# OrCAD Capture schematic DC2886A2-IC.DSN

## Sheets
1 PAGE1: size C; company: ANALOG DEVICES; note: DEMO BOARD BILL OF MATERIALS; note: HIGH POWER POLY-PHASE BI-DIRECTIONAL SUPPLY/CHARGER
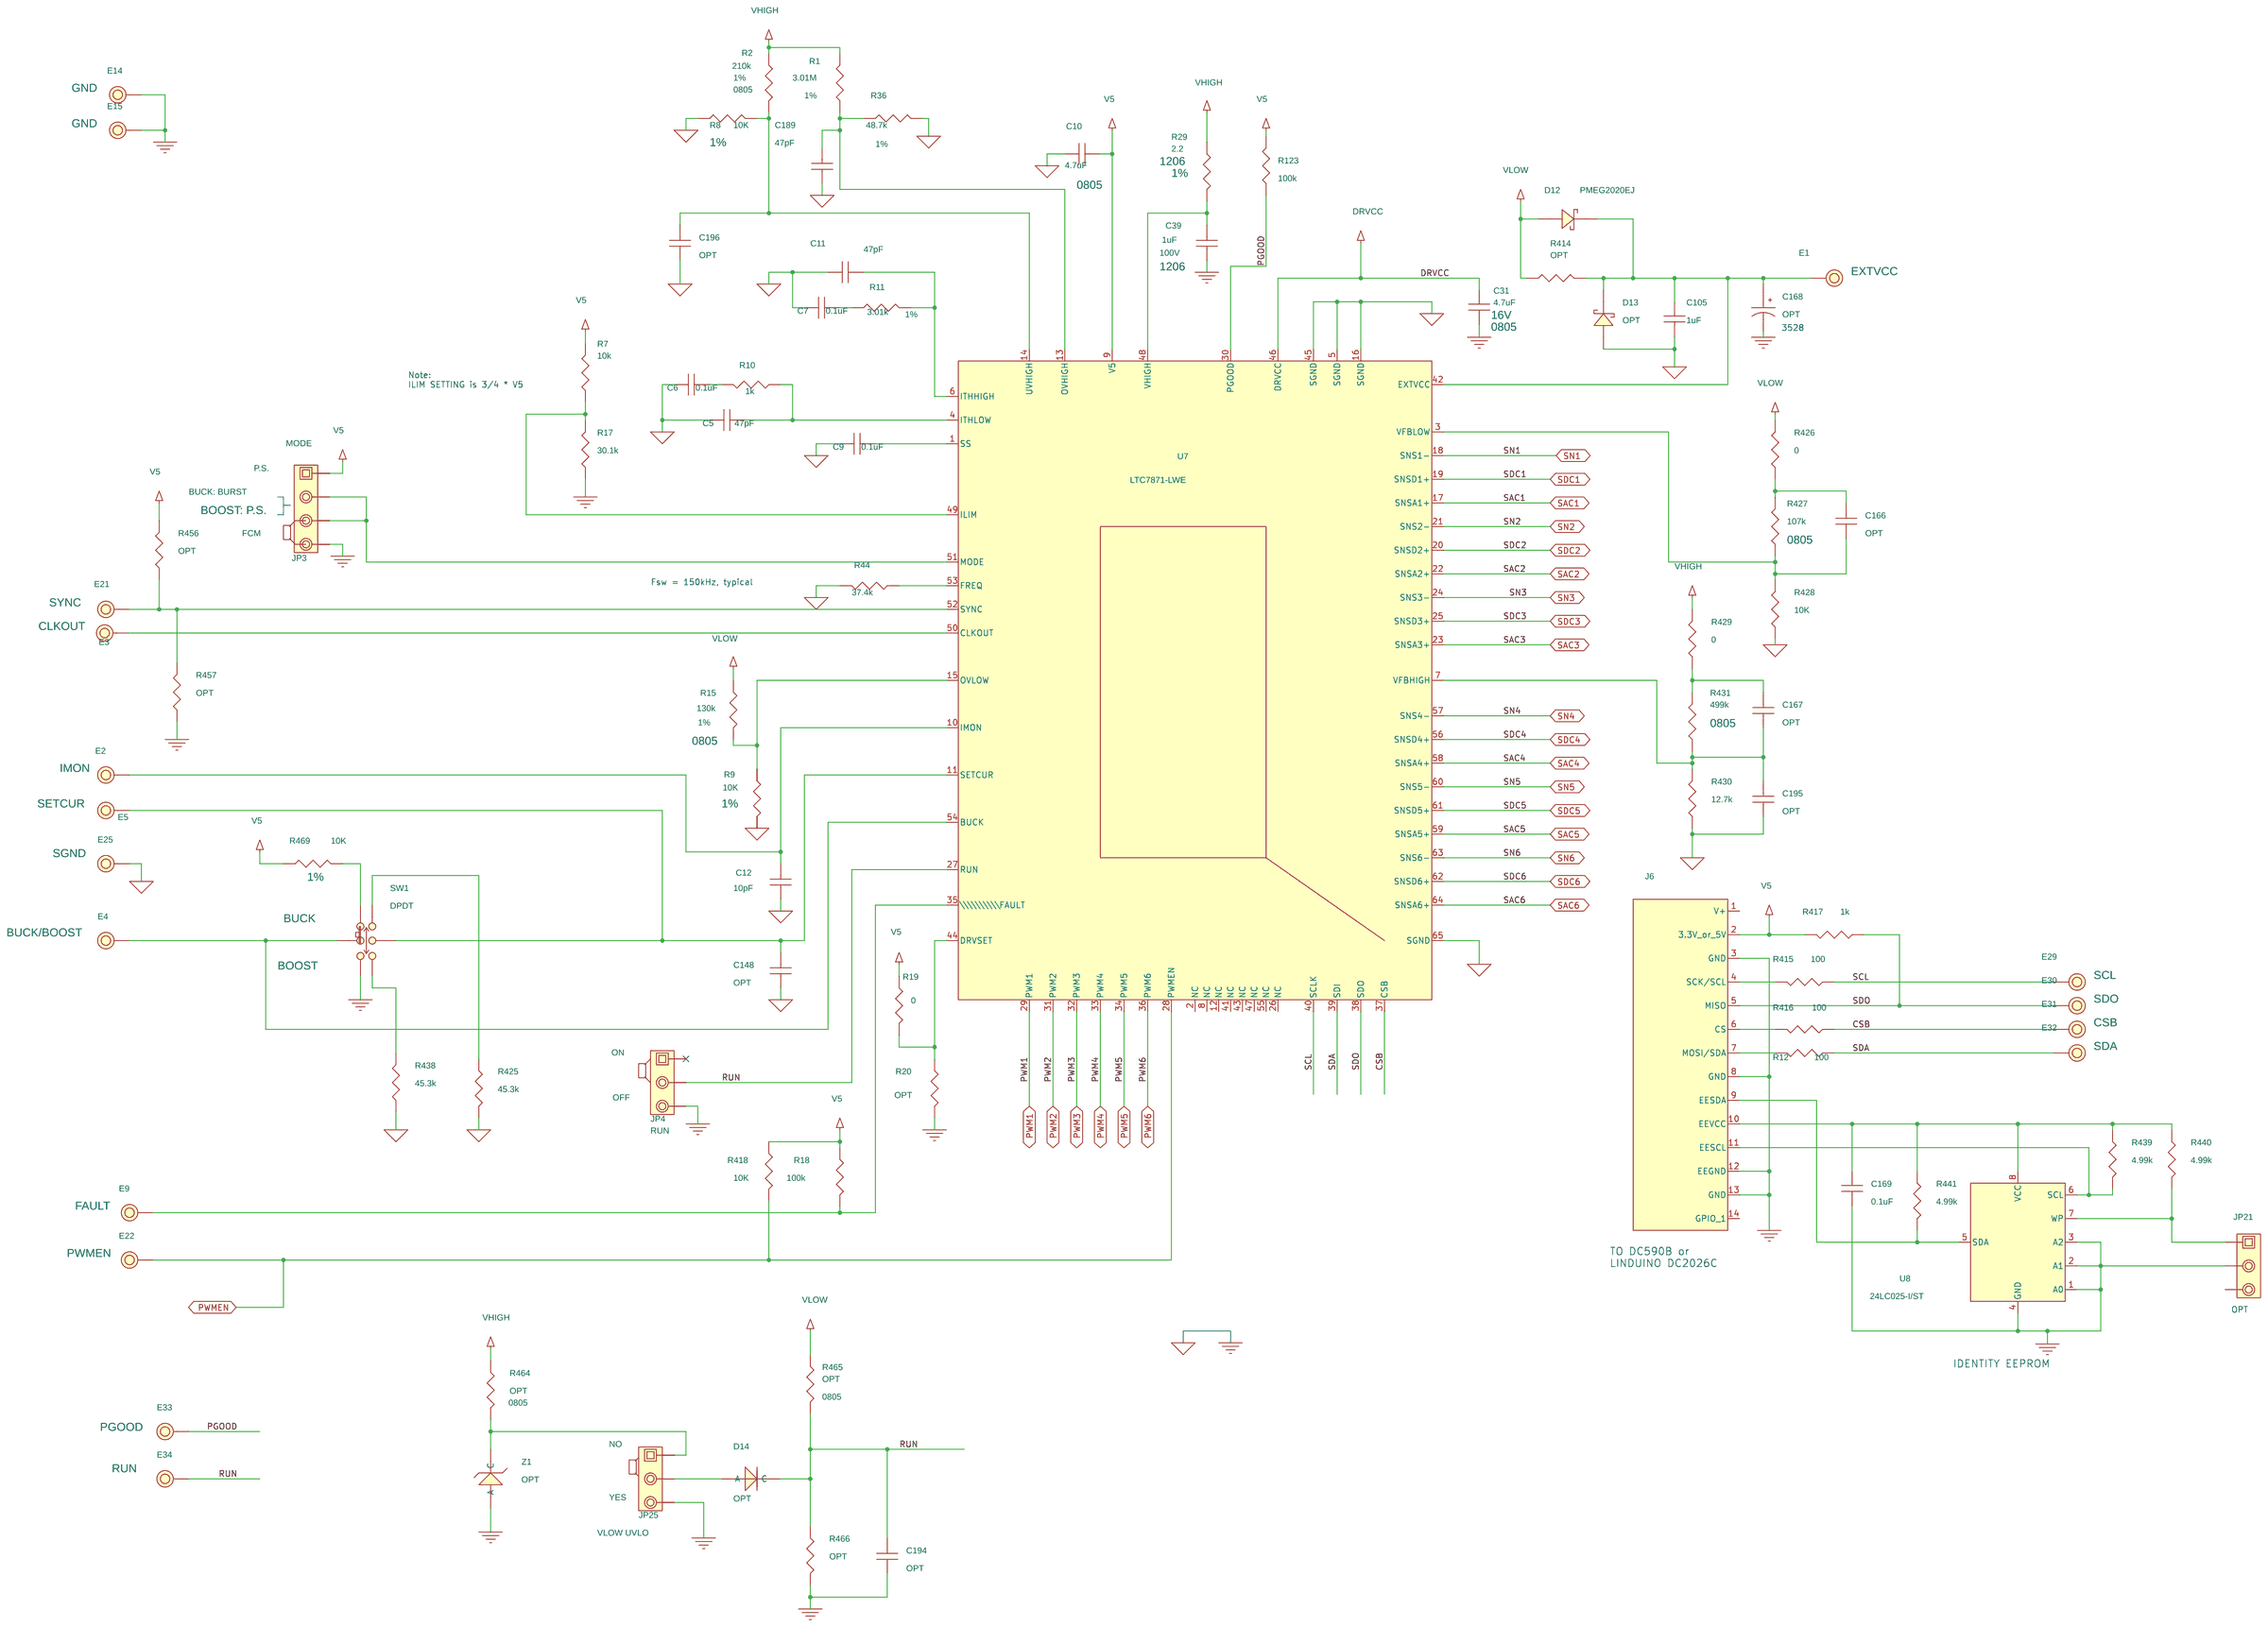
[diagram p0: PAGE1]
2 PAGE2: size C
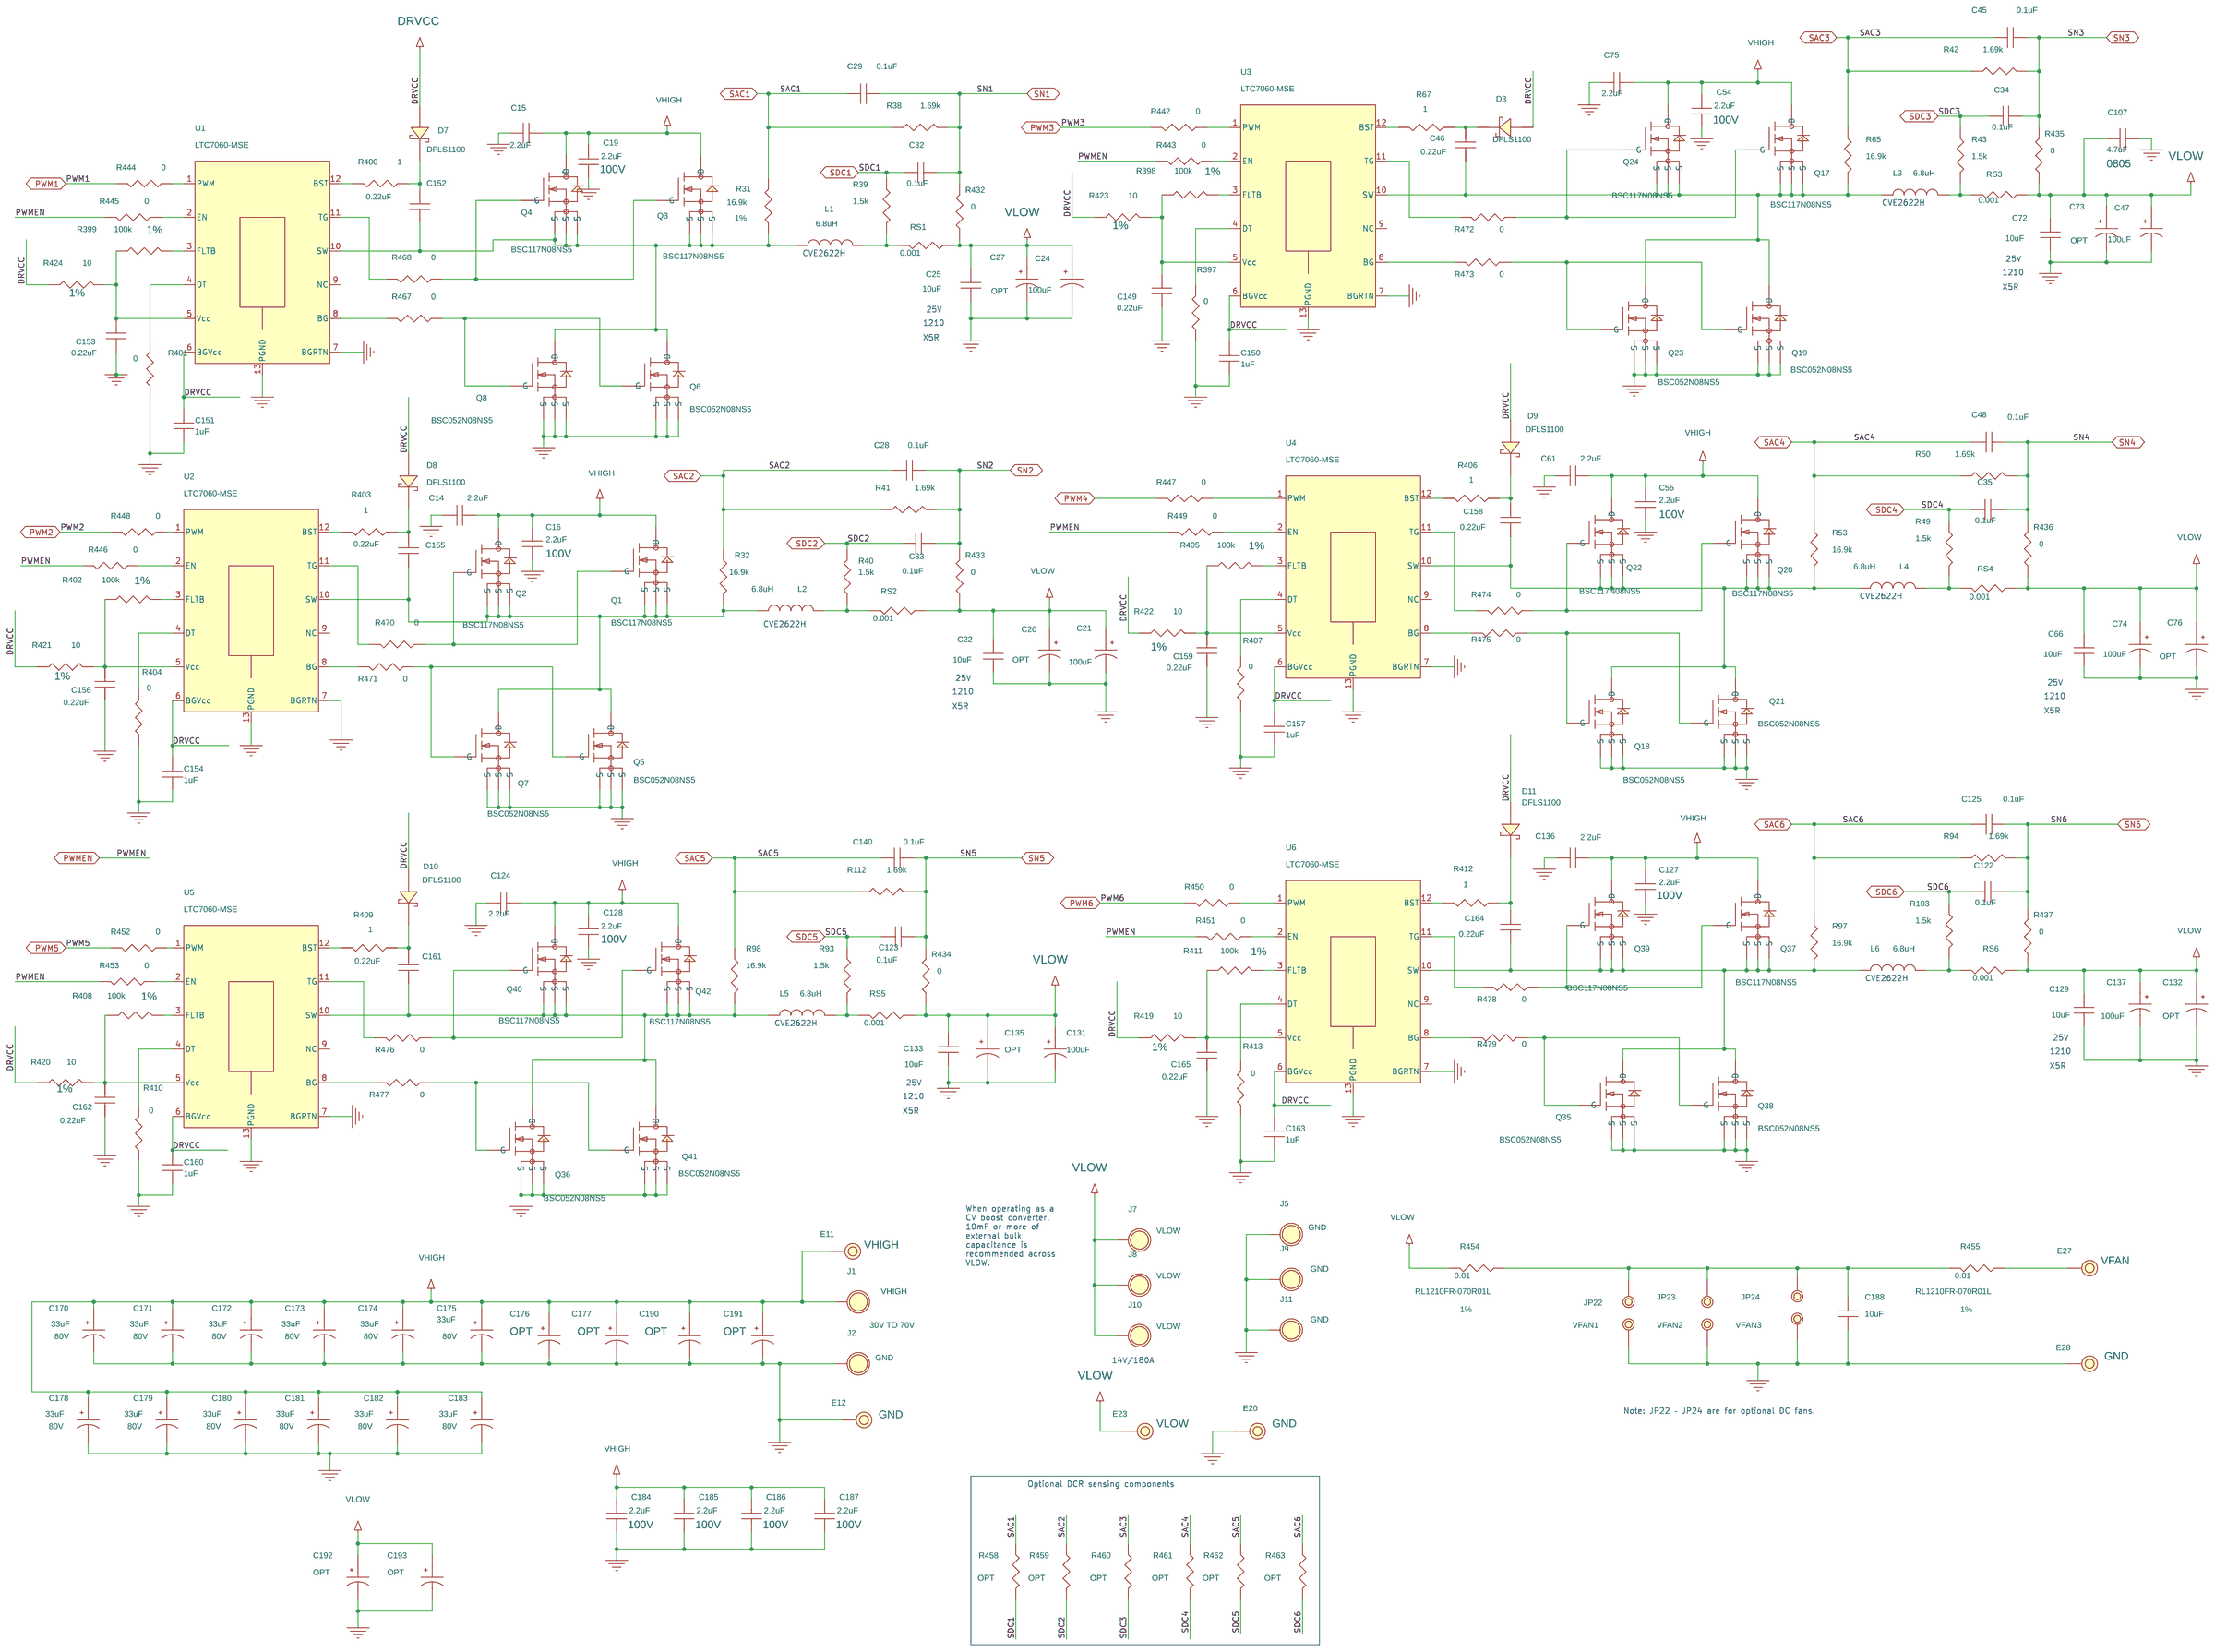
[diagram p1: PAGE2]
3 PAGE3
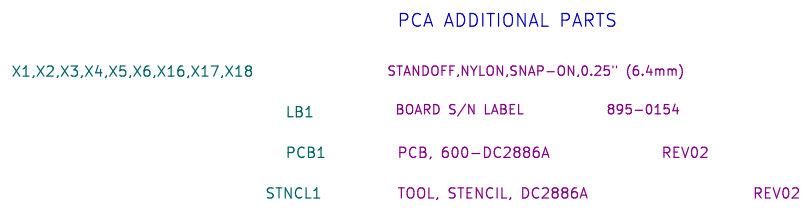
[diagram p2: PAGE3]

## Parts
sheet PAGE1
C5  47pF  [CC0603N]
C6  0.1uF  [CC0603N]
C7  0.1uF  [CC0603N]
C9  0.1uF  [CC0603N]
C10  4.7uF  [CC0805N]
C11  47pF  [CC0603N]
C12  10pF  [CC0603N]
C31  4.7uF  [CC0805N]
C39  1uF  [CC1206N]
C105  1uF  [CC0603N]
C148  OPT  [CC0603N]
C166  OPT  [CC0603N]
C167  OPT  [CC0603N]
C168  OPT  [CAPMP3528N]
C169  0.1uF  [CC0603N]
C189  47pF  [CC0603N]
C194  OPT  [CC0603N]
C195  OPT  [CC0603N]
C196  OPT  [CC0603N]
D12  PMEG2020EJ  [SOD-323F-N]
D13  OPT  [SOD-323N]
D14  OPT  [SOD-323N]
E1  TEST POINT  [MILLMAX2501]
E2  TEST POINT  [MILLMAX2501]
E3  TEST POINT  [MILLMAX2501]
E4  TEST POINT  [MILLMAX2501]
E5  TEST POINT  [MILLMAX2501]
E9  TEST POINT  [MILLMAX2501]
E14  TEST POINT  [MILLMAX2501]
E15  TEST POINT  [MILLMAX2501]
E21  TEST POINT  [MILLMAX2501]
E22  TEST POINT  [MILLMAX2501]
E25  TEST POINT  [MILLMAX2501]
E29  TEST POINT  [MILLMAX2501]
E30  TEST POINT  [MILLMAX2501]
E31  TEST POINT  [MILLMAX2501]
E32  TEST POINT  [MILLMAX2501]
E33  TEST POINT  [MILLMAX2501]
E34  TEST POINT  [MILLMAX2501]
J6  HDR,SHROUDED  [HD2X7-079-MOLEX]
JP3  HDR.  [HD1X4-079]
JP4  HDR  [HD1X3-079]
JP21  HDR  [HD1X3-079]
JP25  HDR  [HD1X3-079]
R1  3.01M  [CR0805N]
R2  210k  [CR0805N]
R7  10k  [CR0603N]
R8  10K  [CR0603N]
R9  10K  [CR0603N]
R10  1k  [CR0603N]
R11  3.01k  [CR0603N]
R12  100  [CR0603N]
R15  130k  [CR0805N]
R17  30.1k  [CR0603N]
R18  100k  [CR0603N]
R19  0  [CR0603N]
R20  OPT  [CR0603N]
R29  2.2  [CR1206N]
R36  48.7k  [CR0603N]
R44  37.4k  [CR0603N]
R123  100k  [CR0603N]
R414  OPT  [CR0603N]
R415  100  [CR0603N]
R416  100  [CR0603N]
R417  100  [CR0603N]
R418  10K  [CR0603N]
R425  45.3k  [CR0603N]
R426  0  [CR0603N]
R427  107k  [CR0805N]
R428  10K  [CR0603N]
R429  0  [CR0603N]
R430  12.7k  [CR0603N]
R431  499k  [CR0805N]
R438  45.3k  [CR0603N]
R439  4.99k  [CR0603N]
R440  4.99k  [CR0603N]
R441  4.99k  [CR0603N]
R456  OPT  [CR0603N]
R457  OPT  [CR0603N]
R464  OPT  [CR0805N]
R465  OPT  [CR0805N]
R466  OPT  [CR0805N]
R469  10K  [CR0603N]
SW1  DPDT  [CK-JS202011CQN]
U7  LTC7871-LWE  [LTC-LWE-64-1982]
U8  24LC025-I/ST  [MO-153AA_N]
XJP3  SHUNT
XJP10  SHUNT
XJP11  SHUNT
Z1  OPT  [SOD-123N]
sheet PAGE2
C14  2.2uF  [CC1210N]
C15  2.2uF  [CC1210N]
C16  2.2uF  [CC1210N]
C19  2.2uF  [CC1210N]
C20  OPT  [USER_ASSIGNED]
C21  100uF  [PANASONIC_ZA_6.3X7.7]
C22  10uF  [CC1210N]
C24  100uF  [PANASONIC_ZA_6.3X7.7]
C25  10uF  [CC1210N]
C27  OPT  [USER_ASSIGNED]
C28  0.1uF  [CC0603N]
C29  0.1uF  [CC0603N]
C32  0.1uF  [CC0603N]
C33  0.1uF  [CC0603N]
C34  0.1uF  [CC0603N]
C35  0.1uF  [CC0603N]
C45  0.1uF  [CC0603N]
C46  0.22uF  [CC0603N]
C47  100uF  [PANASONIC_ZA_6.3X7.7]
C48  0.1uF  [CC0603N]
C54  2.2uF  [CC1210N]
C55  2.2uF  [CC1210N]
C61  2.2uF  [CC1210N]
C66  10uF  [CC1210N]
C72  10uF  [CC1210N]
C73  OPT  [USER_ASSIGNED]
C74  100uF  [PANASONIC_ZA_6.3X7.7]
C75  2.2uF  [CC1210N]
C76  OPT  [USER_ASSIGNED]
C107  4.7uF  [CC0805N]
C122  0.1uF  [CC0603N]
C123  0.1uF  [CC0603N]
C124  2.2uF  [CC1210N]
C125  0.1uF  [CC0603N]
C127  2.2uF  [CC1210N]
C128  2.2uF  [CC1210N]
C129  10uF  [CC1210N]
C131  100uF  [PANASONIC_ZA_6.3X7.7]
C132  OPT  [USER_ASSIGNED]
C133  10uF  [CC1210N]
C135  OPT  [USER_ASSIGNED]
C136  2.2uF  [CC1210N]
C137  100uF  [PANASONIC_ZA_6.3X7.7]
C140  0.1uF  [CC0603N]
C149  0.22uF  [CC0603N]
C150  1uF  [CC0603N]
C151  1uF  [CC0603N]
C152  0.22uF  [CC0603N]
C153  0.22uF  [CC0603N]
C154  1uF  [CC0603N]
C155  0.22uF  [CC0603N]
C156  0.22uF  [CC0603N]
C157  1uF  [CC0603N]
C158  0.22uF  [CC0603N]
C159  0.22uF  [CC0603N]
C160  1uF  [CC0603N]
C161  0.22uF  [CC0603N]
C162  0.22uF  [CC0603N]
C163  1uF  [CC0603N]
C164  0.22uF  [CC0603N]
C165  0.22uF  [CC0603N]
C170  33uF  [PANASONIC_ZC_10X10.2]
C171  33uF  [PANASONIC_ZC_10X10.2]
C172  33uF  [PANASONIC_ZC_10X10.2]
C173  33uF  [PANASONIC_ZC_10X10.2]
C174  33uF  [PANASONIC_ZC_10X10.2]
C175  33uF  [PANASONIC_ZC_10X10.2]
C176  100uF  [SUNCON_CE-KX_16X16.5]
C177  100uF  [SUNCON_CE-KX_16X16.5]
C178  33uF  [PANASONIC_ZC_10X10.2]
C179  33uF  [PANASONIC_ZC_10X10.2]
C180  33uF  [PANASONIC_ZC_10X10.2]
C181  33uF  [PANASONIC_ZC_10X10.2]
C182  33uF  [PANASONIC_ZC_10X10.2]
C183  33uF  [PANASONIC_ZC_10X10.2]
C184  2.2uF  [CC1210N]
C185  2.2uF  [CC1210N]
C186  2.2uF  [CC1210N]
C187  2.2uF  [CC1210N]
C188  10uF  [CC1210N]
C190  100uF  [SUNCON_CE-KX_16X16.5]
C191  100uF  [SUNCON_CE-KX_16X16.5]
C192  OPT  [USER_ASSIGNED]
C193  OPT  [USER_ASSIGNED]
D3  DFLS1100  [POWERDI-123]
D7  DFLS1100  [POWERDI-123]
D8  DFLS1100  [POWERDI-123]
D9  DFLS1100  [POWERDI-123]
D10  DFLS1100  [POWERDI-123]
D11  DFLS1100  [POWERDI-123]
E11  TEST POINT  [MILLMAX2501]
E12  TEST POINT  [MILLMAX2501]
E20  TEST POINT  [MILLMAX2501]
E23  TEST POINT  [MILLMAX2501]
E27  TEST POINT  [MILLMAX2501]
E28  TEST POINT  [MILLMAX2501]
J1  STUD,#10-32  [PENN-KFH-032]
J2  STUD,#10-32  [PENN-KFH-032]
J5  STUD,#10-32  [PENN-KFH-032]
J7  STUD,#10-32  [PENN-KFH-032]
J8  STUD,#10-32  [PENN-KFH-032]
J9  STUD,#10-32  [PENN-KFH-032]
J10  STUD,#10-32  [PENN-KFH-032]
J11  STUD,#10-32  [PENN-KFH-032]
JP22  HDR  [HD1X2-100]
JP23  HDR  [HD1X2-100]
JP24  HDR  [HD1X2-100]
L1  6.8uH  [SAGAMI-CVE2622HA-6R8M-R]
L2  6.8uH  [SAGAMI-CVE2622HA-6R8M-R]
L3  6.8uH  [SAGAMI-CVE2622HA-6R8M-R]
L4  6.8uH  [SAGAMI-CVE2622HA-6R8M-R]
L5  6.8uH  [SAGAMI-CVE2622HA-6R8M-R]
L6  6.8uH  [SAGAMI-CVE2622HA-6R8M-R]
Q1  BSC117N08NS5  [INFINEON-PG-TDSON-8]
Q2  BSC117N08NS5  [INFINEON-PG-TDSON-8]
Q3  BSC117N08NS5  [INFINEON-PG-TDSON-8]
Q4  BSC117N08NS5  [INFINEON-PG-TDSON-8]
Q5  BSC052N08NS5  [INFINEON-PG-TDSON-8]
Q6  BSC052N08NS5  [INFINEON-PG-TDSON-8]
Q7  BSC052N08NS5  [INFINEON-PG-TDSON-8]
Q8  BSC052N08NS5  [INFINEON-PG-TDSON-8]
Q17  BSC117N08NS5  [INFINEON-PG-TDSON-8]
Q18  BSC052N08NS5  [INFINEON-PG-TDSON-8]
Q19  BSC052N08NS5  [INFINEON-PG-TDSON-8]
Q20  BSC117N08NS5  [INFINEON-PG-TDSON-8]
Q21  BSC052N08NS5  [INFINEON-PG-TDSON-8]
Q22  BSC117N08NS5  [INFINEON-PG-TDSON-8]
Q23  BSC052N08NS5  [INFINEON-PG-TDSON-8]
Q24  BSC117N08NS5  [INFINEON-PG-TDSON-8]
Q35  BSC052N08NS5  [INFINEON-PG-TDSON-8]
Q36  BSC052N08NS5  [INFINEON-PG-TDSON-8]
Q37  BSC117N08NS5  [INFINEON-PG-TDSON-8]
Q38  BSC052N08NS5  [INFINEON-PG-TDSON-8]
Q39  BSC117N08NS5  [INFINEON-PG-TDSON-8]
Q40  BSC117N08NS5  [INFINEON-PG-TDSON-8]
Q41  BSC052N08NS5  [INFINEON-PG-TDSON-8]
Q42  BSC117N08NS5  [INFINEON-PG-TDSON-8]
R31  16.9k  [CR0805N]
R32  16.9k  [CR0805N]
R38  1.69k  [CR0603N]
R39  1.5k  [CR0603N]
R40  1.5k  [CR0603N]
R41  1.69k  [CR0603N]
R42  1.69k  [CR0603N]
R43  1.5k  [CR0603N]
R49  1.5k  [CR0603N]
R50  1.69k  [CR0603N]
R53  16.9k  [CR0805N]
R65  16.9k  [CR0805N]
R67  1  [CR0603N]
R93  1.5k  [CR0603N]
R94  1.69k  [CR0603N]
R97  16.9k  [CR0805N]
R98  16.9k  [CR0805N]
R103  1.5k  [CR0603N]
R112  1.69k  [CR0603N]
R397  0  [CR0603N]
R398  100k  [CR0603N]
R399  100k  [CR0603N]
R400  1  [CR0603N]
R401  0  [CR0603N]
R402  100k  [CR0603N]
R403  1  [CR0603N]
R404  0  [CR0603N]
R405  100k  [CR0603N]
R406  1  [CR0603N]
R407  0  [CR0603N]
R408  100k  [CR0603N]
R409  1  [CR0603N]
R410  0  [CR0603N]
R411  100k  [CR0603N]
R412  1  [CR0603N]
R413  0  [CR0603N]
R419  10  [CR0603N]
R420  10  [CR0603N]
R421  10  [CR0603N]
R422  10  [CR0603N]
R423  10  [CR0603N]
R424  10  [CR0603N]
R432  0  [CR0603N]
R433  0  [CR0603N]
R434  0  [CR0603N]
R435  0  [CR0603N]
R436  0  [CR0603N]
R437  0  [CR0603N]
R442  0  [CR0603N]
R443  0  [CR0603N]
R444  0  [CR0603N]
R445  0  [CR0603N]
R446  0  [CR0603N]
R447  0  [CR0603N]
R448  0  [CR0603N]
R449  0  [CR0603N]
R450  0  [CR0603N]
R451  0  [CR0603N]
R452  0  [CR0603N]
R453  0  [CR0603N]
R454  0.01  [CR1210N]
R455  0.01  [CR1210N]
R458  OPT  [CR0603N]
R459  OPT  [CR0603N]
R460  OPT  [CR0603N]
R461  OPT  [CR0603N]
R462  OPT  [CR0603N]
R463  OPT  [CR0603N]
R467  0  [CR0603N]
R468  0  [CR0603N]
R470  0  [CR0603N]
R471  0  [CR0603N]
R472  0  [CR0603N]
R473  0  [CR0603N]
R474  0  [CR0603N]
R475  0  [CR0603N]
R476  0  [CR0603N]
R477  0  [CR0603N]
R478  0  [CR0603N]
R479  0  [CR0603N]
RS1  0.001  [VISHAY-WSL2512-T87]
RS2  0.001  [VISHAY-WSL2512-T87]
RS3  0.001  [VISHAY-WSL2512-T87]
RS4  0.001  [VISHAY-WSL2512-T87]
RS5  0.001  [VISHAY-WSL2512-T87]
RS6  0.001  [VISHAY-WSL2512-T87]
U1  LTC7060-MSE  [LTC-MSE-12-1666]
U2  LTC7060-MSE  [LTC-MSE-12-1666]
U3  LTC7060-MSE  [LTC-MSE-12-1666]
U4  LTC7060-MSE  [LTC-MSE-12-1666]
U5  LTC7060-MSE  [LTC-MSE-12-1666]
U6  LTC7060-MSE  [LTC-MSE-12-1666]
sheet PAGE3
LB1  LABEL  [895-0154_REV01]
PCB1  PCB, 600-DC2886A
STNCL1  TOOL, STENCIL, DC2886A
X1,X2,X3,X4,X5,X6,X16,X17,X18  STANDOFF  [MTG-8831]

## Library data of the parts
C5 = CAP: CAP.,47pF,C0G,50V,10%,0603; CLASS: DISCRETE; Dielectric Type: C0G; FPLIST: CC0603N,CC0603L,CC0603M; Inventory Qty: 4550; Manufacturer: AVX; Manufacturer PN: 06035A470KAT2A; PART_NUMBER: 150-3408; Package Size: 0603; Part Number: AVX 06035A470KAT2A; Rated Voltage: 50V; Tolerance: 10%
C6 C7 C9 = CAP: CAP.,0.1uF,X7R,25V,10%,0603,AEC-Q200; CLASS: DISCRETE; Dielectric Type: X7R; FPLIST: CC0603N,CC0603L,CC0603M; Inventory Qty: 5452; Manufacturer: AVX; Manufacturer PN: 06033C104K4T4A; PART_NUMBER: 150-0439; Package Size: 0603; Part Number: AVX 06031C103KAT2A; Rated Voltage: 25V; Tolerance: 10%
C10 C31 C107 = CAP: CAP.,4.7uF,X7R,16V,10%,0805; CLASS: DISCRETE; Dielectric Type: X7R; FPLIST: CC0805N,CC0805L,CC0805M; Inventory Qty: 55550; Manufacturer: AVX; Manufacturer PN: 0805YC475KAT2A; PART_NUMBER: 150-2085; Package Size: 0805; Part Number: AVX 0805YC475KAT2A; Rated Voltage: 16V; Tolerance: 10%
C11 C189 = CAP: CAP.,47pF,C0G,50V,5%,0603; CLASS: DISCRETE; Dielectric Type: C0G; FPLIST: CC0603N,CC0603L,CC0603M; Inventory Qty: 42764; Manufacturer: MURATA; Manufacturer PN: GRM1885C1H470JA01D; PART_NUMBER: 150-0054; Package Size: 0603; Rated Voltage: 50V; Tolerance: 5%
C12 = CAP: CAP.,10pF,C0G,100V,+/-0.1pF,0603; CLASS: DISCRETE; Dielectric Type: C0G; FPLIST: CC0603N,CC0603L,CC0603M; Inventory Qty: 190; Manufacturer: AVX; Manufacturer PN: 06031A100BAT2A; PART_NUMBER: 150-2528; Package Size: 0603; Part Number: AVX 06031A100KAT2A / AVX; Rated Voltage: 100V; Tolerance: +/-0.1pF
C39 = CAP: CAP.,1uF,X7R,100V,10%,1206; CLASS: DISCRETE; Dielectric Type: X7R; FPLIST: CC1206N,CC1206L,CC1206M; Inventory Qty: 11126; Manufacturer: AVX; Manufacturer PN: 12061C105KAT2A; PART_NUMBER: 150-3438; Package Size: 1206; Rated Voltage: 100V; Tolerance: 10%
C105 = CAP: CAP.,1uF,X7R,25V,10%,0603,AEC-Q200; CLASS: DISCRETE; Dielectric Type: X7R; FPLIST: CC0603N,CC0603L,CC0603M; Inventory Qty: 38139; Manufacturer: MURATA; Manufacturer PN: GCM188R71E105KA64D; PART_NUMBER: 150-0291; Package Size: 0603; Part Number: MURATA GRM188R71E105KA12D; Rated Voltage: 25V; Tolerance: 10%
C148 = CAP: CAP., OPTION, 0603; CLASS: DISCRETE; FPLIST: CC0603N,CC0603L,CC0603M; PART_NUMBER: 150-3038; Package Size: 0603; Package Type: SMD; Part Number: AVX 06031A100KAT2A / AVX
C166 C167 = CAP: CAP., OPTION, 0603; CLASS: DISCRETE; FPLIST: CC0603N,CC0603L,CC0603M; PART_NUMBER: 150-3038; Package Size: 0603; Package Type: SMD; Part Number: AVX 06035A470KAT2A
C168 = CAP_P_ALT: CAP.,15uF,TANT,16V,20%,3528; BOM Notes: NO STUFF; CLASS: DISCRETE; Dielectric Type: TANT; FPLIST: CAPMP3528N,CAPMP3528L,CAPMP3528M; Inventory Qty: 1000; Manufacturer: KEMET; Manufacturer PN: T521B156M016ATE090; PART_NUMBER: 150-0768; Package Size: 3528; Rated Voltage: 16V; Tolerance: 20%
C169 = CAP: CAP.,0.1uF,X7R,25V,10%,0603,AEC-Q200; CLASS: DISCRETE; Dielectric Type: X7R; FPLIST: CC0603N,CC0603L,CC0603M; Inventory Qty: 5452; Manufacturer: AVX; Manufacturer PN: 06033C104K4T4A; PART_NUMBER: 150-0439; Package Size: 0603; Rated Voltage: 25V; Tolerance: 10%
C194-C196 = CAP: CAP., OPTION, 0603; CLASS: DISCRETE; FPLIST: CC0603N,CC0603L,CC0603M; PART_NUMBER: 150-3038; Package Size: 0603; Package Type: SMD; Part Number: AVX 06031C103KAT2A
D12 = DIODE_SCHOTTKY_A_ALT: DIODE,SCHOTTKY,20V,2A,SOD-323F; CLASS: DISCRETE; FPLIST: SOD-323F-N,SOD-323F-L,SOD-323F-M; Inventory Qty: 3000; Manufacturer: NEXPERIA; Manufacturer PN: PMEG2020EJ,115; PART_NUMBER: 210-0082; Package Size: SOD-323F; Package Type: SOD-323F; Part Number: DIODES INC. DFLS1100-7; Rated Voltage or Zener Voltage: 20V
D13 = DIODE_SCHOTTKY_A_ALT: DIODE, OPTION, SOD-323; CLASS: DISCRETE; FPLIST: SOD-323N,SOD-323L,SOD-323M; PART_NUMBER: 210-0118; Package Type: SOD-323; Part Number: DIODES INC. DFLS1100-7
D14 = DIODE_A: DIODE, OPTION, SOD-323; CLASS: DISCRETE; FPLIST: SOD-323N,SOD-323L,SOD-323M; PART_NUMBER: 210-0118; Package Type: SOD-323
E1 = TESTPOINT_.219_MILL-MAX_2501: TEST POINT,TURRET,0.094" MTG. HOLE,PCB 0.062" THK; CLASS: IO; FPLIST: MILLMAX2501,MILLMAX2501_ALT1; Inventory Qty: 600261; Manufacturer: MILL-MAX; Manufacturer PN: 2501-2-00-80-00-00-07-0; PART_FIELD_01: EXTVCC; PART_NUMBER: 260-0003; Part Number: MIIL-MAX 2501-2-00-80-00-00-07-0
E2 = TESTPOINT_.219_MILL-MAX_2501: TEST POINT,TURRET,0.094" MTG. HOLE,PCB 0.062" THK; CLASS: IO; FPLIST: MILLMAX2501,MILLMAX2501_ALT1; Inventory Qty: 600261; Manufacturer: MILL-MAX; Manufacturer PN: 2501-2-00-80-00-00-07-0; PART_FIELD_01: IMON; PART_NUMBER: 260-0003; Part Number: MIIL-MAX 2501-2-00-80-00-00-07-0
E3 = TESTPOINT_.219_MILL-MAX_2501: TEST POINT,TURRET,0.094" MTG. HOLE,PCB 0.062" THK; CLASS: IO; FPLIST: MILLMAX2501,MILLMAX2501_ALT1; Inventory Qty: 600261; Manufacturer: MILL-MAX; Manufacturer PN: 2501-2-00-80-00-00-07-0; PART_FIELD_01: CLKOUT; PART_NUMBER: 260-0003; Part Number: MIIL-MAX 2501-2-00-80-00-00-07-0
E4 = TESTPOINT_.219_MILL-MAX_2501: TEST POINT,TURRET,0.094" MTG. HOLE,PCB 0.062" THK; CLASS: IO; FPLIST: MILLMAX2501,MILLMAX2501_ALT1; Inventory Qty: 600261; Manufacturer: MILL-MAX; Manufacturer PN: 2501-2-00-80-00-00-07-0; PART_FIELD_01: BUCK/BOOST; PART_NUMBER: 260-0003; Part Number: MIIL-MAX 2501-2-00-80-00-00-07-0
E5 = TESTPOINT_.219_MILL-MAX_2501: TEST POINT,TURRET,0.094" MTG. HOLE,PCB 0.062" THK; CLASS: IO; FPLIST: MILLMAX2501,MILLMAX2501_ALT1; Inventory Qty: 600261; Manufacturer: MILL-MAX; Manufacturer PN: 2501-2-00-80-00-00-07-0; PART_FIELD_01: SETCUR; PART_NUMBER: 260-0003; Part Number: MIIL-MAX 2501-2-00-80-00-00-07-0
E9 = TESTPOINT_.219_MILL-MAX_2501: TEST POINT,TURRET,0.094" MTG. HOLE,PCB 0.062" THK; CLASS: IO; FPLIST: MILLMAX2501,MILLMAX2501_ALT1; Inventory Qty: 600261; Manufacturer: MILL-MAX; Manufacturer PN: 2501-2-00-80-00-00-07-0; PART_FIELD_01: FAULT; PART_NUMBER: 260-0003; Part Number: MIIL-MAX 2501-2-00-80-00-00-07-0
E12 E14 E15 E20 E28 = TESTPOINT_.219_MILL-MAX_2501: TEST POINT,TURRET,0.094" MTG. HOLE,PCB 0.062" THK; CLASS: IO; FPLIST: MILLMAX2501,MILLMAX2501_ALT1; Inventory Qty: 600261; Manufacturer: MILL-MAX; Manufacturer PN: 2501-2-00-80-00-00-07-0; PART_FIELD_01: GND; PART_NUMBER: 260-0003; Part Number: MIIL-MAX 2501-2-00-80-00-00-07-0
E21 = TESTPOINT_.219_MILL-MAX_2501: TEST POINT,TURRET,0.094" MTG. HOLE,PCB 0.062" THK; CLASS: IO; FPLIST: MILLMAX2501,MILLMAX2501_ALT1; Inventory Qty: 600261; Manufacturer: MILL-MAX; Manufacturer PN: 2501-2-00-80-00-00-07-0; PART_FIELD_01: SYNC; PART_NUMBER: 260-0003; Part Number: MIIL-MAX 2501-2-00-80-00-00-07-0
E22 = TESTPOINT_.219_MILL-MAX_2501: TEST POINT,TURRET,0.094" MTG. HOLE,PCB 0.062" THK; CLASS: IO; FPLIST: MILLMAX2501,MILLMAX2501_ALT1; Inventory Qty: 600261; Manufacturer: MILL-MAX; Manufacturer PN: 2501-2-00-80-00-00-07-0; PART_FIELD_01: PWMEN; PART_NUMBER: 260-0003; Part Number: MIIL-MAX 2501-2-00-80-00-00-07-0
E25 = TESTPOINT_.219_MILL-MAX_2501: TEST POINT,TURRET,0.094" MTG. HOLE,PCB 0.062" THK; CLASS: IO; FPLIST: MILLMAX2501,MILLMAX2501_ALT1; Inventory Qty: 600261; Manufacturer: MILL-MAX; Manufacturer PN: 2501-2-00-80-00-00-07-0; PART_FIELD_01: SGND; PART_NUMBER: 260-0003; Part Number: MIIL-MAX 2501-2-00-80-00-00-07-0
E29 = TESTPOINT_.219_MILL-MAX_2501: TEST POINT,TURRET,0.094" MTG. HOLE,PCB 0.062" THK; CLASS: IO; FPLIST: MILLMAX2501,MILLMAX2501_ALT1; Inventory Qty: 600261; Manufacturer: MILL-MAX; Manufacturer PN: 2501-2-00-80-00-00-07-0; PART_FIELD_01: SCL; PART_NUMBER: 260-0003; Part Number: MIIL-MAX 2501-2-00-80-00-00-07-0
E30 = TESTPOINT_.219_MILL-MAX_2501: TEST POINT,TURRET,0.094" MTG. HOLE,PCB 0.062" THK; CLASS: IO; FPLIST: MILLMAX2501,MILLMAX2501_ALT1; Inventory Qty: 600261; Manufacturer: MILL-MAX; Manufacturer PN: 2501-2-00-80-00-00-07-0; PART_FIELD_01: SDO; PART_NUMBER: 260-0003; Part Number: MIIL-MAX 2501-2-00-80-00-00-07-0
E31 = TESTPOINT_.219_MILL-MAX_2501: TEST POINT,TURRET,0.094" MTG. HOLE,PCB 0.062" THK; CLASS: IO; FPLIST: MILLMAX2501,MILLMAX2501_ALT1; Inventory Qty: 600261; Manufacturer: MILL-MAX; Manufacturer PN: 2501-2-00-80-00-00-07-0; PART_FIELD_01: CSB; PART_NUMBER: 260-0003; Part Number: MIIL-MAX 2501-2-00-80-00-00-07-0
E32 = TESTPOINT_.219_MILL-MAX_2501: TEST POINT,TURRET,0.094" MTG. HOLE,PCB 0.062" THK; CLASS: IO; FPLIST: MILLMAX2501,MILLMAX2501_ALT1; Inventory Qty: 600261; Manufacturer: MILL-MAX; Manufacturer PN: 2501-2-00-80-00-00-07-0; PART_FIELD_01: SDA; PART_NUMBER: 260-0003; Part Number: MIIL-MAX 2501-2-00-80-00-00-07-0
E33 = TESTPOINT_.219_MILL-MAX_2501: TEST POINT,TURRET,0.094" MTG. HOLE,PCB 0.062" THK; CLASS: IO; FPLIST: MILLMAX2501,MILLMAX2501_ALT1; Inventory Qty: 600261; Manufacturer: MILL-MAX; Manufacturer PN: 2501-2-00-80-00-00-07-0; PART_FIELD_01: PGOOD; PART_NUMBER: 260-0003; Part Number: MIIL-MAX 2501-2-00-80-00-00-07-0
E34 = TESTPOINT_.219_MILL-MAX_2501: TEST POINT,TURRET,0.094" MTG. HOLE,PCB 0.062" THK; CLASS: IO; FPLIST: MILLMAX2501,MILLMAX2501_ALT1; Inventory Qty: 600261; Manufacturer: MILL-MAX; Manufacturer PN: 2501-2-00-80-00-00-07-0; PART_FIELD_01: RUN; PART_NUMBER: 260-0003; Part Number: MIIL-MAX 2501-2-00-80-00-00-07-0
J6 = DC590_ALT2: CONN.,HDR,SHROUDED,MALE,2x7,2mm,VERT,ST,THT; CLASS: IO; Inventory Qty: 20712; Manufacturer: MOLEX; Manufacturer PN: 87831-1420; PART_NUMBER: 250-0403
JP3 = HDR1X4_ALT1: CONN.,HDR.,MALE,1x4,2mm,THT, STR; 10th Part Field: BUCK: BURST; 12th Part Field: FCM; 13tht Part Field: MODE; 8th part fieid: BOOST: P.S.; 9th Part Field: P.S.; CLASS: IO; Inventory Qty: 13310; Manufacturer: SULLINS CONNECTOR SOLUTIONS; Manufacturer PN: NRPN041PAEN-RC; PART_NUMBER: 250-0431
JP4 JP21 = 1X3_A: CONN.,HDR,MALE,1x3,2mm,VERT,ST,THT,NO SUBS. ALLOWED; 11th Part Field: OFF; 12th Part Field: RUN; 9th Part Field: ON; CLASS: IO; Inventory Qty: 8344; Manufacturer: SAMTEC; Manufacturer PN: TMM-103-02-L-S; PART_NUMBER: 250-0638
JP25 = 1X3_A: CONN.,HDR,MALE,1x3,2mm,VERT,ST,THT,NO SUBS. ALLOWED; 11th Part Field: YES; 12th Part Field: VLOW UVLO; 9th Part Field: NO; CLASS: IO; Inventory Qty: 8344; Manufacturer: SAMTEC; Manufacturer PN: TMM-103-02-L-S; PART_NUMBER: 250-0638
R1 = RES: RES.,3.01M OHMS,1%,1/8W,0805,AEC-Q200; CLASS: DISCRETE; FPLIST: CR0805N,CR0805L,CR0805M; Inventory Qty: 10000; Manufacturer: VISHAY; Manufacturer PN: CRCW08053M01FKEA; PART_NUMBER: 100-1588; Package Size: 0805; Part Number: VISHAY CRCW0603649KFKEA; Rated Power: 1/8W; Temperature Coefficient: +/-100ppm; Tolerance: 1%
R2 = RES: RES.,210k OHMS,1%,1/8W,0805,AEC-Q200; CLASS: DISCRETE; FPLIST: CR0805N,CR0805L,CR0805M; Inventory Qty: 0; Manufacturer: VISHAY; Manufacturer PN: CRCW0805210KFKEA; PART_NUMBER: 100-1643; Package Size: 0805; Part Number: VISHAY CRCW0603243KFKEA; Rated Power: 1/8W; Temperature Coefficient: +/-100ppm; Tolerance: 1%
R7 = RES: RES.,10k OHMS,5%,1/10W,0603; CLASS: DISCRETE; FPLIST: CR0603N,CR0603L,CR0603M; Inventory Qty: 32772; Manufacturer: SAMSUNG; Manufacturer PN: RC1608J103CS; PART_NUMBER: 100-0005; Package Size: 0603; Part Number: VISHAY CRCW060310K0FKEA; Rated Power: 1/10W; Temperature Coefficient: 100ppm/C; Tolerance: 5%
R8 R9 R469 = RES: RES.,10K OHMS,1%,1/10W,0603,AEC-Q200; CLASS: DISCRETE; FPLIST: CR0603N,CR0603L,CR0603M; Inventory Qty: 44473; Manufacturer: PANASONIC; Manufacturer PN: ERJ3EKF1002V; PART_NUMBER: 100-0602; Package Size: 0603; Part Number: VISHAY CRCW060310K0FKEA; Rated Power: 1/10W; Temperature Coefficient: 100PPM; Tolerance: 1%
R10 = RES: RES.,1k OHMS,5%,1/10W,0603; CLASS: DISCRETE; FPLIST: CR0603N,CR0603L,CR0603M; Inventory Qty: 35096; Manufacturer: SAMSUNG; Manufacturer PN: RC1608J102CS; PART_NUMBER: 100-0020; Package Size: 0603; Part Number: VISHAY CRCW06033K01FKEA; Rated Power: 1/10W; Temperature Coefficient: 100ppm/C; Tolerance: 5%
R11 = RES: RES.,3.01k OHMS,1%,1/10W,0603; CLASS: DISCRETE; FPLIST: CR0603N,CR0603L,CR0603M; Inventory Qty: 37506; Manufacturer: VISHAY; Manufacturer PN: CRCW06033K01FKEA; PART_NUMBER: 100-2477; Package Size: 0603; Part Number: VISHAY CRCW06034K53FKEA; Rated Power: 1/10W; Temperature Coefficient: 100ppm/C; Tolerance: 1%
R12 R415 R416 = RES: RES.,100 OHMS,1%,1/10W,0603,AEC-Q200; CLASS: DISCRETE; FPLIST: CR0603N,CR0603L,CR0603M; Inventory Qty: 78288; Manufacturer: PANASONIC; Manufacturer PN: ERJ3EKF1000V; PART_NUMBER: 100-2586; Package Size: 0603; Part Number: OPTION; Rated Power: 1/10W; Temperature Coefficient: 100ppm; Tolerance: 1%
R15 = RES: RES.,130k OHMS,1%,1/8W,0805; CLASS: DISCRETE; FPLIST: CR0805N,CR0805L,CR0805M; Inventory Qty: 600; Manufacturer: NIC; Manufacturer PN: NRC10F1303TRF; PART_NUMBER: 100-2851; Package Size: 0805; Part Number: VISHAY CRCW0603110KFKEA; Rated Power: 1/8W; Temperature Coefficient: 100ppm; Tolerance: 1%
R17 = RES: RES.,30.1k OHMS,1%,1/10W,0603,AEC-Q200; CLASS: DISCRETE; FPLIST: CR0603N,CR0603L,CR0603M; Inventory Qty: 34610; Manufacturer: VISHAY; Manufacturer PN: CRCW060330K1FKEA; PART_NUMBER: 100-2524; Package Size: 0603; Part Number: VISHAY CRCW060310K0FKEA; Rated Power: 1/10W; Temperature Coefficient: 100ppm/C; Tolerance: 1%
R18 = RES: RES.,100k OHMS,1%,1/10W,0603,AEC-Q200; CLASS: DISCRETE; FPLIST: CR0603N,CR0603L,CR0603M; Inventory Qty: 185563; Manufacturer: VISHAY; Manufacturer PN: CRCW0603100KFKEA; PART_NUMBER: 100-0343; Package Size: 0603; Part Number: VISHAY CRCW0603100KJNEA; Rated Power: 1/10W; Temperature Coefficient: +/-100ppm; Tolerance: 1%
R19 = RES: RES.,0 OHM,1/10W,0603; CLASS: DISCRETE; FPLIST: CR0603N,CR0603L,CR0603M; Inventory Qty: 57520; Manufacturer: BOURNS; Manufacturer PN: CR0603-J/-000ELF; PART_NUMBER: 100-2621; Package Size: 0603; Part Number: OPTION; Rated Power: 1/10W
R20 R458-R463 = RES: RES., OPTION, 0603; CLASS: DISCRETE; FPLIST: CR0603N,CR0603L,CR0603M; PART_NUMBER: 100-2374; Package Size: 0603; Part Number: OPTION
R29 = RES: RES.,2.2 OHMS,1%,1/4W,1206,AEC-Q200; CLASS: DISCRETE; FPLIST: CR1206N,CR1206L,CR1206M; Inventory Qty: 29775; Manufacturer: VISHAY; Manufacturer PN: CRCW12062R20FKEA; PART_NUMBER: 100-0778; Package Size: 1206; Part Number: VISHAY CRCW12062R20FKEA; Rated Power: 1/4W; Temperature Coefficient: 100ppm; Tolerance: 1%
R36 = RES: RES.,48.7k OHMS,1%,1/10W,0603,AEC-Q200; CLASS: DISCRETE; FPLIST: CR0603N,CR0603L,CR0603M; Inventory Qty: 18680; Manufacturer: VISHAY; Manufacturer PN: CRCW060348K7FKEA; PART_NUMBER: 100-0260; Package Size: 0603; Part Number: VISHAY CRCW060310K0FKEA; Rated Power: 1/10W; Temperature Coefficient: 100ppm/C; Tolerance: 1%
R44 = RES: RES.,37.4k OHMS,1%,1/10W,0603,AEC-Q200; CLASS: DISCRETE; FPLIST: CR0603N,CR0603L,CR0603M; Inventory Qty: 1500; Manufacturer: PANASONIC; Manufacturer PN: ERJ-3EKF3742; PART_NUMBER: 100-0862; Package Size: 0603; Part Number: VISHAY CRCW060334K0FKEA; Rated Power: 1/10W; Temperature Coefficient: +/-100PPM; Tolerance: 1%
R123 = RES: RES.,100k OHMS,1%,1/10W,0603,AEC-Q200; CLASS: DISCRETE; FPLIST: CR0603N,CR0603L,CR0603M; Inventory Qty: 185563; Manufacturer: VISHAY; Manufacturer PN: CRCW0603100KFKEA; PART_NUMBER: 100-0343; Package Size: 0603; Part Number: VISHAY CRCW06030000Z0EA; Rated Power: 1/10W; Temperature Coefficient: +/-100ppm; Tolerance: 1%
R414 R456 R457 = RES: RES., OPTION, 0603; CLASS: DISCRETE; FPLIST: CR0603N,CR0603L,CR0603M; PART_NUMBER: 100-2374; Package Size: 0603; Part Number: VISHAY CRCW06030000Z0EA
R417 = RES: RES.,100 OHMS,1%,1/10W,0603,AEC-Q200; 1st Part Field: 1k; CLASS: DISCRETE; FPLIST: CR0603N,CR0603L,CR0603M; Inventory Qty: 78288; Manufacturer: PANASONIC; Manufacturer PN: ERJ3EKF1000V; PART_NUMBER: 100-2586; Package Size: 0603; Part Number: OPTION; Rated Power: 1/10W; Temperature Coefficient: 100ppm; Tolerance: 1%
R418 = RES: RES.,10K OHMS,1%,1/10W,0603,AEC-Q200; CLASS: DISCRETE; FPLIST: CR0603N,CR0603L,CR0603M; Inventory Qty: 44473; Manufacturer: PANASONIC; Manufacturer PN: ERJ3EKF1002V; PART_NUMBER: 100-0602; Package Size: 0603; Part Number: VISHAY CRCW0603100KJNEA; Rated Power: 1/10W; Temperature Coefficient: 100PPM; Tolerance: 1%
R425 R438 = RES: RES.,45.3k OHMS,1%,1/10W,0603,AEC-Q200; CLASS: DISCRETE; FPLIST: CR0603N,CR0603L,CR0603M; Inventory Qty: 20355; Manufacturer: PANASONIC; Manufacturer PN: ERJ3EKF4532V; PART_NUMBER: 100-2684; Package Size: 0603; Rated Power: 1/10W; Temperature Coefficient: 100ppm; Tolerance: 1%
R426 R429 R467 R468 R470-R479 = RES: RES.,0 OHM,1/10W,0603; CLASS: DISCRETE; FPLIST: CR0603N,CR0603L,CR0603M; Inventory Qty: 57520; Manufacturer: BOURNS; Manufacturer PN: CR0603-J/-000ELF; PART_NUMBER: 100-2621; Package Size: 0603; Part Number: VISHAY CRCW06030000Z0EA; Rated Power: 1/10W
R427 = RES: RES.,107k OHMS,1%,1/8W,0805; CLASS: DISCRETE; FPLIST: CR0805N,CR0805L,CR0805M; Inventory Qty: 15000; Manufacturer: VISHAY; Manufacturer PN: CRCW0805107KFKEA; PART_NUMBER: 100-3001; Package Size: 0805; Part Number: VISHAY CRCW06030000Z0EA; Rated Power: 1/8W; Temperature Coefficient: +/-100PPM; Tolerance: 1%
R428 = RES: RES.,10K OHMS,1%,1/10W,0603,AEC-Q200; CLASS: DISCRETE; FPLIST: CR0603N,CR0603L,CR0603M; Inventory Qty: 44473; Manufacturer: PANASONIC; Manufacturer PN: ERJ3EKF1002V; PART_NUMBER: 100-0602; Package Size: 0603; Part Number: VISHAY CRCW06030000Z0EA; Rated Power: 1/10W; Temperature Coefficient: 100PPM; Tolerance: 1%
R430 = RES: RES.,12.7k OHMS,1%,1/10W,0603,AEC-Q200; CLASS: DISCRETE; FPLIST: CR0603N,CR0603L,CR0603M; Inventory Qty: 8842; Manufacturer: PANASONIC; Manufacturer PN: ERJ3EKF1272V; PART_NUMBER: 100-0377; Package Size: 0603; Part Number: VISHAY CRCW06030000Z0EA; Rated Power: 1/10W; Temperature Coefficient: 100ppm/C; Tolerance: 1%
R431 = RES: RES.,499k OHMS,1%,1/8W,0805,AEC-Q200; CLASS: DISCRETE; FPLIST: CR0805N,CR0805L,CR0805M; Inventory Qty: 34780; Manufacturer: NIC; Manufacturer PN: NRC10F4993TRF; PART_NUMBER: 100-0777; Package Size: 0805; Part Number: VISHAY CRCW06030000Z0EA; Rated Power: 1/8W; Temperature Coefficient: 100ppm; Tolerance: 1%
R439-R441 = RES: RES.,4.99k OHMS,1%,1/10W,0603; CLASS: DISCRETE; FPLIST: CR0603N,CR0603L,CR0603M; Inventory Qty: 72949; Manufacturer: PANASONIC; Manufacturer PN: ERJ3EKF4991V; PART_NUMBER: 100-0121; Package Size: 0603; Rated Power: 1/10W; Temperature Coefficient: 100ppm/C; Tolerance: 1%
R464-R466 = RES: RES., OPTION, 0805; CLASS: DISCRETE; FPLIST: CR0805N,CR0805L,CR0805M; PART_NUMBER: 100-2558; Package Size: 0805
SW1 = SW-DPDT-JS202011CQN_ALT1_1: SWITCH,SLIDE,DPDT,0.3A,6VDC,PTH; CLASS: DISCRETE; Inventory Qty: 32201; Manufacturer: C&K; Manufacturer PN: JS202011CQN; PART_FIELD_01: BUCK; PART_FIELD_02: BOOST; PART_NUMBER: 430-0039
U7 = LTC-LWE: IC,HIGH POWER POLY-PHASE,BI-DIRECTIONAL SUPPLY/CHARGER; CLASS: IC; Inventory Qty: 0; Manufacturer: ANALOG DEVICES; Manufacturer PN: LTC7871ELWE#PBF; PART_NUMBER: LTC7871ELWE#PBF; Package Size: 10mmx10mm; Package Type: BI-DIRECTIONAL SUPPLY/CHARGER
U8 = 24LC025-I_ST_TSSOP-8_D: IC, MEMORY,EEPROM,2Kb (256x8),TSSOP-8,400kHz; CLASS: IC; FPLIST: TSSOP-8N,TSSOP-8L,TSSOP-8M,MICROCHIP-TSSOP-8; Inventory Qty: 14751; Manufacturer: Microchip; PART_NUMBER: 380-0087; Package Size: TSSOP-8; Package Type: TSSOP-8
XJP3 XJP10 XJP11 = SHUNT_2MM: CONN.,SHUNT,FEMALE,2-POS,2mm; CLASS: IO; Inventory Qty: 277825; Manufacturer: SAMTEC; Manufacturer PN: 2SN-BK-G; PART_NUMBER: 250-0419
Z1 = ZENER: DIODE, OPTION, SOD-123; CLASS: DISCRETE; FPLIST: SOD-123N,SOD-123L,SOD-123M; PART_NUMBER: 210-0115; Package Type: SOD-123
C14-C16 C19 C54 C55 C61 C75 C124 C127 C128 C136 C184-C187 = CAP: CAP.,2.2uF,X7R,100V,10%,1210; CLASS: DISCRETE; Dielectric Type: X7R; FPLIST: CC1210N,CC1210L,CC1210M; Inventory Qty: 47416; Manufacturer: MURATA; Manufacturer PN: GRM32ER72A225KA35L; PART_NUMBER: 150-3049; Package Size: 1210; Part Number: AVX 12101C225KAT2A; Rated Voltage: 100V; Tolerance: 10%
C20 C27 C73 C76 C132 C135 = CAP_P_ALT: CAP.,OPTION,ALUM. ELECT.,SMD; CLASS: DISCRETE; PART_NUMBER: 150-3571; Package Type: SMD; Part Number: OPTION
C21 C24 C47 C74 C131 C137 = CAP_P_ALT: CAP.,100uF,ALUM POLY HYB,25V,20%,6.3x7.7mm,D8,SMD,RADIAL,AEC-Q200; CLASS: DISCRETE; Dielectric Type: ALUM POLY HYB; Inventory Qty: 12960; Manufacturer: PANASONIC; Manufacturer PN: EEHZA1E101XP; PART_NUMBER: 150-2391; Package Size: 6.3x7.7mm,D8,SMD,RADIAL; Part Number: PANASONIC EEHZA1E101XP; Rated Voltage: 25V; Tolerance: 20%
C22 C25 C66 C72 C129 C133 C188 = CAP: CAP.,10uF,X7R,25V,10%,1210; CLASS: DISCRETE; Dielectric Type: X7R; FPLIST: CC1210N,CC1210L,CC1210M; Inventory Qty: 11903; Manufacturer: AVX; Manufacturer PN: 12103C106KAT2A; PART_NUMBER: 150-0282; Package Size: 1210; Part Number: MURATA GRM31CR71E106KA12L; Rated Voltage: 25V; Tolerance: 10%
C28 C29 C45 C48 C125 C140 = CAP: CAP.,0.1uF,X7R,25V,10%,0603,AEC-Q200; CLASS: DISCRETE; Dielectric Type: X7R; FPLIST: CC0603N,CC0603L,CC0603M; Inventory Qty: 5452; Manufacturer: AVX; Manufacturer PN: 06033C104K4T4A; PART_NUMBER: 150-0439; Package Size: 0603; Part Number: AVX 06033D224KAT2A; Rated Voltage: 25V; Tolerance: 10%
C32-C35 C122 C123 = CAP: CAP.,0.1uF,X7R,25V,10%,0603,AEC-Q200; CLASS: DISCRETE; Dielectric Type: X7R; FPLIST: CC0603N,CC0603L,CC0603M; Inventory Qty: 5452; Manufacturer: AVX; Manufacturer PN: 06033C104K4T4A; PART_NUMBER: 150-0439; Package Size: 0603; Part Number: OPTION; Rated Voltage: 25V; Tolerance: 10%
C46 C149 C152 C153 C155 C156 C158 C159 C161 C162 C164 C165 = CAP: CAP.,0.22uF,X7R,25V,10%,0603; CLASS: DISCRETE; Dielectric Type: X7R; FPLIST: CC0603N,CC0603L,CC0603M; Inventory Qty: 27121; Manufacturer: MURATA; Manufacturer PN: GRM188R71E224KA88D; PART_NUMBER: 150-0320; Package Size: 0603; Part Number: AVX 06033D224KAT2A; Rated Voltage: 25V; Tolerance: 10%
C150 C151 C154 C157 C160 C163 = CAP: CAP.,1uF,X7R,25V,10%,0603,AEC-Q200; CLASS: DISCRETE; Dielectric Type: X7R; FPLIST: CC0603N,CC0603L,CC0603M; Inventory Qty: 38139; Manufacturer: MURATA; Manufacturer PN: GCM188R71E105KA64D; PART_NUMBER: 150-0291; Package Size: 0603; Part Number: AVX 06033D224KAT2A; Rated Voltage: 25V; Tolerance: 10%
C170-C175 C178-C183 = CAP_P_ALT: CAP.,33uF,ALUM ELECT HYB,80V,20%,10x10.2mm,SMD,RADIAL,AEC-Q200; CLASS: DISCRETE; Dielectric Type: ALUM ELECT HYB; Inventory Qty: 6487; Manufacturer: PANASONIC; Manufacturer PN: EEHZC1K330P; PART_NUMBER: 150-1298; Package Size: 10x10.2mm,SMD,RADIAL; Part Number: PANASONIC EEHZC1K330P; Rated Voltage: 80V; Tolerance: 20%
C176 C177 C190 C191 = CAP_P_ALT: CAP.,100uF,ALUM. ELECT.,100V,10%,16x16.5mm SMD; BOM Notes: NO STUFF; CLASS: DISCRETE; Dielectric Type: ALUM. ELECT.; Inventory Qty: 2010; Manufacturer: SUN ELECTRONIC INDUSTRIES CORP; Manufacturer PN: 100CE100KXT+D; PART_NUMBER: 150-2387; Package Size: 16x16.5mm SMD; Part Number: SUN ELECT. 100CE100KXT; Rated Voltage: 100V; Tolerance: 10%; filed 1: OPT
C192 C193 = CAP_P_ALT: CAP.,OPTION,ALUM. ELECT.,SMD; CLASS: DISCRETE; PART_NUMBER: 150-0497; Package Type: SMD; Part Number: SUN ELECT. 100CE100KXT
D3 D7-D11 = DIODE_SCHOTTKY_A_ALT: DIODE,SCHOTTKY,100V,1A,POWERDI-123; CLASS: DISCRETE; Inventory Qty: 15666; Manufacturer: DIODES INC.; Manufacturer PN: DFLS1100-7; Max Forward Current or Rated Power: 1A; PART_NUMBER: 210-0044; Package Size: POWERDI®123; Part Number: DIODES INC. DFLS1100-7; Rated Voltage or Zener Voltage: 100V
E11 = TESTPOINT_.219_MILL-MAX_2501: TEST POINT,TURRET,0.094" MTG. HOLE,PCB 0.062" THK; CLASS: IO; FPLIST: MILLMAX2501,MILLMAX2501_ALT1; Inventory Qty: 600261; Manufacturer: MILL-MAX; Manufacturer PN: 2501-2-00-80-00-00-07-0; PART_FIELD_01: VHIGH; PART_NUMBER: 260-0003; Part Number: MIIL-MAX 2501-2-00-80-00-00-07-0
E23 = TESTPOINT_.219_MILL-MAX_2501: TEST POINT,TURRET,0.094" MTG. HOLE,PCB 0.062" THK; CLASS: IO; FPLIST: MILLMAX2501,MILLMAX2501_ALT1; Inventory Qty: 600261; Manufacturer: MILL-MAX; Manufacturer PN: 2501-2-00-80-00-00-07-0; PART_FIELD_01: VLOW; PART_NUMBER: 260-0003; Part Number: MIIL-MAX 2501-2-00-80-00-00-07-0
E27 = TESTPOINT_.219_MILL-MAX_2501: TEST POINT,TURRET,0.094" MTG. HOLE,PCB 0.062" THK; CLASS: IO; FPLIST: MILLMAX2501,MILLMAX2501_ALT1; Inventory Qty: 600261; Manufacturer: MILL-MAX; Manufacturer PN: 2501-2-00-80-00-00-07-0; PART_FIELD_01: VFAN; PART_NUMBER: 260-0003; Part Number: MIIL-MAX 2501-2-00-80-00-00-07-0
J1 = PEM-KFH_A: EVAL BOARD STUD HARDWARE SET, #10-32; 10th Part Field: 30V TO 70V; 11th Part Field: 11th???; 9th Part Field: VHIGH; CLASS: DISCRETE; Comments: CONSISTS OF QTY(1) STUD, 769-0012; QTY(1) RING LUG, 769-0013;QTY(2) HEX NUT,BRASS,761-0013; QTY(1) WASHER,#10 LOCK, 762-0021; Manufacturer: ANALOG DEVICES; Manufacturer PN: 720-0010; PART_NUMBER: 720-0010; Part Number: PEM KFH-032-10
J2 J5 J9 J11 = PEM-KFH_A: EVAL BOARD STUD HARDWARE SET, #10-32; 10th Part Field: 5 - 24V #; 11th Part Field: 11th???; 9th Part Field: GND; CLASS: DISCRETE; Comments: CONSISTS OF QTY(1) STUD, 769-0012; QTY(1) RING LUG, 769-0013;QTY(2) HEX NUT,BRASS,761-0013; QTY(1) WASHER,#10 LOCK, 762-0021; Manufacturer: ANALOG DEVICES; Manufacturer PN: 720-0010; PART_NUMBER: 720-0010; Part Number: PEM KFH-032-10
J7 J8 J10 = PEM-KFH_A: EVAL BOARD STUD HARDWARE SET, #10-32; 10th Part Field: 30V UP TO 75V; 11th Part Field: 11th???; 9th Part Field: VLOW; CLASS: DISCRETE; Comments: CONSISTS OF QTY(1) STUD, 769-0012; QTY(1) RING LUG, 769-0013;QTY(2) HEX NUT,BRASS,761-0013; QTY(1) WASHER,#10 LOCK, 762-0021; Manufacturer: ANALOG DEVICES; Manufacturer PN: 720-0010; PART_NUMBER: 720-0010; Part Number: PEM KFH-032-10
JP22 = HDR1X2_ALT1_2: CONN.,HDR,MALE,1x2,2.54mm,VERT,ST,THT; 9th Part Field: VFAN1; CLASS: IO; Inventory Qty: 990; Manufacturer: WURTH ELEKTRONIK; Manufacturer PN: 61300211121; PART_NUMBER: 250-0766
JP23 = HDR1X2_ALT1_1: CONN.,HDR,MALE,1x2,2.54mm,VERT,ST,THT; 9th Part Field: VFAN2; CLASS: IO; Inventory Qty: 990; Manufacturer: WURTH ELEKTRONIK; Manufacturer PN: 61300211121; PART_NUMBER: 250-0766
JP24 = HDR1X2_ALT1: CONN.,HDR,MALE,1x2,2.54mm,VERT,ST,THT; 9th Part Field: VFAN3; CLASS: IO; Inventory Qty: 990; Manufacturer: WURTH ELEKTRONIK; Manufacturer PN: 61300211121; PART_NUMBER: 250-0766
L1-L6 = IND_ALT: IND.,6.8uH,PWR,CHOKE,20%,41A,2mOHMS,4-TERM,THT,AEC-Q200; CLASS: DISCRETE; Inventory Qty: 1480; Manufacturer: SAGAMI ELEC CO., LTD.; Manufacturer PN: CVE2622C-6R8M-R; PART_NUMBER: 200-0520; Package Size: 4-TERM,THT; Part Number: WURTH 7443641000 / COILCRAFT SER2918H-103; Tolerance: 20%
Q1-Q4 Q17 Q20 Q22 Q24 Q37 Q39 Q40 Q42 = 5P_N-CH_TYPE1D: XSTR.,MOSFET,N-CH,80V,49A,PG-TDSON-8; CLASS: DISCRETE; Inventory Qty: 18752; Manufacturer: INFINEON; PART_NUMBER: 240-0254; Package Size: PG-TDSON-8; Package Type: PG-TDSON-8; Rated Voltage: 80V
Q5-Q8 Q18 Q19 Q21 Q23 Q35 Q36 Q38 Q41 = 5P_N-CH_TYPE1D: XSTR.,MOSFET,N-CH,80V,95A,TDSON-8; CLASS: DISCRETE; Inventory Qty: 5000; Manufacturer: INFINEON; PART_NUMBER: 240-0396; Package Size: PG-TDSON-8; Package Type: TDSON-8; Rated Voltage: 80V
R31 = RES: RES.,16.9k OHMS,1%,1/8W,0805,AEC-Q200; CLASS: DISCRETE; FPLIST: CR08053N,CR0805L,CR0805M; Inventory Qty: 5000; Manufacturer: STACKPOLE ELECTRONICS, INC.; Manufacturer PN: RMCF0805FT16K9; PART_NUMBER: 100-1656; Package Size: 0805; Part Number: VISHAY CRCW06034K99FKEA; Rated Power: 1/8W; Temperature Coefficient: +/-100ppm; Tolerance: 1%
R32 R53 R65 R97 R98 = RES: RES.,16.9k OHMS,1%,1/8W,0805,AEC-Q200; CLASS: DISCRETE; FPLIST: CR08053N,CR0805L,CR0805M; Inventory Qty: 5000; Manufacturer: STACKPOLE ELECTRONICS, INC.; Manufacturer PN: RMCF0805FT16K9; PART_NUMBER: 100-1656; Package Size: 0805; Rated Power: 1/8W; Temperature Coefficient: +/-100ppm; Tolerance: 1%
R38 R41 R42 R50 R94 R112 = RES: RES.,1.69k OHMS,1%,1/10W,0603,AEC-Q200; CLASS: DISCRETE; FPLIST: CR0603N,CR0603L,CR0603M; Inventory Qty: 11723; Manufacturer: NIC; Manufacturer PN: NRC06F1691TRF; PART_NUMBER: 100-2797; Package Size: 0603; Rated Power: 1/10W; Temperature Coefficient: 100ppm/C; Tolerance: 1%
R39 R40 R43 R49 R93 R103 = RES: RES.,1.5k OHMS,1%,1/10W,0603; CLASS: DISCRETE; FPLIST: CR0603N,CR0603L,CR0603M; Inventory Qty: 13500; Manufacturer: NIC; Manufacturer PN: NRC06F1501TRF; PART_NUMBER: 100-0310; Package Size: 0603; Rated Power: 1/10W; Temperature Coefficient: 100ppm/C; Tolerance: 1%
R67 R400 R403 R406 R409 R412 = RES: RES.,1 OHM,1%,1/10W,0603; CLASS: DISCRETE; FPLIST: CR0603N,CR0603L,CR0603M; Inventory Qty: 15668; Manufacturer: YAGEO; Manufacturer PN: RC0603FR-071RL; PART_NUMBER: 100-0163; Package Size: 0603; Part Number: VISHAY CRCW06030000Z0EA; Rated Power: 1/10W; Temperature Coefficient: 200ppm/C; Tolerance: 1%
R397 R401 R404 R407 R410 R413 R432-R437 R442-R453 = RES: RES.,0 OHM,1/10W,0603; CLASS: DISCRETE; FPLIST: CR0603N,CR0603L,CR0603M; Inventory Qty: 57520; Manufacturer: BOURNS; Manufacturer PN: CR0603-J/-000ELF; PART_NUMBER: 100-2621; Package Size: 0603; Part Number: VISHAY CRCW0603300RFKEA; Rated Power: 1/10W
R398 R399 R402 R405 R408 R411 = RES: RES.,100k OHMS,1%,1/10W,0603,AEC-Q200; CLASS: DISCRETE; FPLIST: CR0603N,CR0603L,CR0603M; Inventory Qty: 185563; Manufacturer: VISHAY; Manufacturer PN: CRCW0603100KFKEA; PART_NUMBER: 100-0343; Package Size: 0603; Part Number: VISHAY CRCW0603300RFKEA; Rated Power: 1/10W; Temperature Coefficient: +/-100ppm; Tolerance: 1%
R419-R424 = RES: RES.,10 OHMS,1%,1/10W,0603; CLASS: DISCRETE; FPLIST: CR0603N,CR0603L,CR0603M; Inventory Qty: 149594; Manufacturer: VISHAY; Manufacturer PN: CRCW060310R0FKEA; PART_NUMBER: 100-2306; Package Size: 0603; Part Number: VISHAY CRCW0603300RFKEA; Rated Power: 1/10W; Temperature Coefficient: 100ppm/C; Tolerance: 1%
R454 R455 = RES: RES.,0.01 OHM,1%,1/2W,1210,SENSE, AEC-Q200; CLASS: DISCRETE; FPLIST: CR1210N,CR1210L,CR1210M; Inventory Qty: 11100; Manufacturer: YAGEO; Manufacturer PN: RL1210FR-070R01L; PART_NUMBER: 100-0716; Package Size: 1210; Part Number: VISHAY WSL120610L000FEA; Rated Power: 1/2W; Temperature Coefficient: 1500ppm; Tolerance: 1%
RS1-RS6 = RES: RES.,0.001 OHM,1%,1W,2512,METAL,SENSE,AEC-Q200; CLASS: DISCRETE; FPLIST: CR2512N,CR2512L,CR2512M; Inventory Qty: 8478; Manufacturer: VISHAY; Manufacturer PN: WSL25121L000FEA; PART_NUMBER: 100-0477; Package Size: 2512; Part Number: VISHAY WSL20101L000FEA18; Rated Power: 1W; Temperature Coefficient: 275ppm; Tolerance: 1%
U1-U6 = LTC7060-MSE: IC,DC/DC CONVERTER,MSE-12; CLASS: IC; Inventory Qty: 0; Manufacturer: ANALOG DEVICES; Manufacturer PN: LTC7060EMSE#PBF; PART_NUMBER: LTC7060EMSE#PBF; Package Type: MSE-12
LB1 = BLANK_LABEL: LABEL SPEC, DEMO BOARD SERIAL NUMBER; Inventory Qty: 0; Manufacturer: BRADY; Manufacturer PN: THT-96-717-10; PART_FIELD_01: BOARD S/N LABEL; PART_NUMBER: 895-0154
PCB1 = BLANK_PCB_PART: BOM Notes: REV02; CLASS: DISCRETE; Inventory Qty: 0; Manufacturer: ADI APPROVED SUPPLIER; Manufacturer PN: 600-DC2886A; PART_NUMBER: 600-DC2886A
STNCL1 = BLANK_STENCIL_PART: BOM Notes: REV02; CLASS: DISCRETE; Inventory Qty: 0; Manufacturer: ADI APPROVED SUPPLIER; Manufacturer PN: 830-DC2886A; PART_NUMBER: 830-DC2886A
X1,X2,X3,X4,X5,X6,X16,X17,X18 = BLANK_MECHANICAL_PART: STANDOFF,NYLON,SNAP-ON,0.25" (6.4mm); CLASS: DISCRETE; Inventory Qty: 203968; Manufacturer: KEYSTONE; Manufacturer PN: 8831; PART_NUMBER: 763-0006

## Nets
GND: C14.2 C15.1 C16.1 C19.1 C20.2 C21.2 C22.1 C24.2 C25.1 C27.2 C31.2 C39.1 C47.2 C54.1 C55.1 C61.2 C66.1 C72.1 C73.2 C74.2 C75.1 C76.2 C107.2 C124.1 C127.1 C128.1 C129.1 C131.2 C132.2 C133.1 C135.2 C136.2 C137.2 C149.1 C150.1 C151.1 C153.1 C154.1 C156.1 C157.1 C159.1 C160.1 C162.1 C163.1 C165.1 C168.2 C169.2 C170.2 C171.2 C172.2 C173.2 C174.2 C175.2 C176.2 C177.2 C178.2 C179.2 C180.2 C181.2 C182.2 C183.2 C184.1 C185.1 C186.1 C187.1 C188.1 C190.2 C191.2 C192.2 C193.2 C194.1 E12.1 E14.1 E15.1 E20.1 E28.1 J2.1(TP) J5.1(TP) J6.3(GND) J6.8(GND) J6.12(EEGND) J6.13(GND) J9.1(TP) J11.1(TP) JP3.4 JP4.3 JP21.2 JP22.2 JP23.2 JP24.2 JP25.3 Q5.1(S) Q5.2(S) Q5.3(S) Q6.1(S) Q6.2(S) Q6.3(S) Q7.1(S) Q7.2(S) Q7.3(S) Q8.1(S) Q8.2(S) Q8.3(S) Q18.1(S) Q18.2(S) Q18.3(S) Q19.1(S) Q19.2(S) Q19.3(S) Q21.1(S) Q21.2(S) Q21.3(S) Q23.1(S) Q23.2(S) Q23.3(S) Q35.1(S) Q35.2(S) Q35.3(S) Q36.1(S) Q36.2(S) Q36.3(S) Q38.1(S) Q38.2(S) Q38.3(S) Q41.1(S) Q41.2(S) Q41.3(S) R17.1 R20.1 R397.2 R401.2 R404.2 R407.2 R410.2 R413.2 R457.1 R466.1 SW1.6 U1.7(BGRTN) U1.13(PGND) U2.7(BGRTN) U2.13(PGND) U3.7(BGRTN) U3.13(PGND) U4.7(BGRTN) U4.13(PGND) U5.7(BGRTN) U5.13(PGND) U6.7(BGRTN) U6.13(PGND) U8.1(A0) U8.2(A1) U8.3(A2) U8.4(GND) Z1.2(A)
GNDSIGNAL: C5.1 C6.1 C7.1 C9.1 C10.1 C11.1 C12.1 C105.2 C148.1 C189.1 C195.1 C196.1 D13.2(A) E25.1 R8.1 R9.1 R36.1 R44.2 R425.1 R428.1 R430.1 R438.2 U7.5(SGND) U7.16(SGND) U7.45(SGND) U7.65(SGND)
V5: C10.2 J6.2(3.3V_or_5V) JP3.1 R7.2 R18.2 R19.2 R123.2 R417.2 R418.2 R456.2 R469.2 U7.9(V5)
CSB: E31.1 R416.1 U7.37(CSB)
DRVCC: C31.1 C150.2 C151.2 C154.2 C157.2 C160.2 C163.2 D3.2(A) D7.2(A) D8.2(A) D9.2(A) D10.2(A) D11.2(A) R419.2 R420.2 R421.2 R422.2 R423.2 R424.2 U1.6(BGVcc) U2.6(BGVcc) U3.6(BGVcc) U4.6(BGVcc) U5.6(BGVcc) U6.6(BGVcc) U7.46(DRVCC)
PGOOD: E33.1 R123.1 U7.30(PGOOD)
PWM1: R444.1 U7.29(PWM1)
PWM2: R448.1 U7.31(PWM2)
PWM3: R442.1 U7.32(PWM3)
PWM4: R447.1 U7.33(PWM4)
PWM5: R452.1 U7.34(PWM5)
PWM6: R450.1 U7.36(PWM6)
PWMEN: E22.1 R418.1 R443.1 R445.1 R446.1 R449.1 R451.1 R453.1 U7.28(PWMEN)
RUN: C194.2 D14.1(C) E34.1 JP4.2 R465.1 R466.2 U7.27(RUN)
SAC1: C29.1 R31.2 R38.2 R458.2 U7.17(SNSA1+)
SAC2: C28.2 R32.1 R41.1 R459.2 U7.22(SNSA2+)
SAC3: C45.1 R42.2 R65.2 R460.2 U7.23(SNSA3+)
SAC4: C48.2 R50.1 R53.1 R461.2 U7.58(SNSA4+)
SAC5: C140.1 R98.2 R112.2 R462.2 U7.59(SNSA5+)
SAC6: C125.2 R94.1 R97.1 R463.2 U7.64(SNSA6+)
SCL: E29.1 R415.1 U7.40(SCLK)
SDA: E32.1 R12.1 U7.39(SDI)
SDC1: C32.2 R39.2 R458.1 U7.19(SNSD1+)
SDC2: C33.1 R40.2 R459.1 U7.20(SNSD2+)
SDC3: C34.2 R43.2 R460.1 U7.25(SNSD3+)
SDC4: C35.1 R49.2 R461.1 U7.56(SNSD4+)
SDC5: C123.2 R93.2 R462.1 U7.61(SNSD5+)
SDC6: C122.1 R103.2 R463.1 U7.62(SNSD6+)
SDO: E30.1 J6.5(MISO) R417.1 U7.38(SDO)
SN1: C29.2 C32.1 R38.1 R432.1 U7.18(SNS1-)
SN2: C28.1 C33.2 R41.2 R433.1 U7.21(SNS2-)
SN3: C34.1 C45.2 R42.1 R435.1 U7.24(SNS3-)
SN4: C35.2 C48.1 R50.2 R436.1 U7.57(SNS4-)
SN5: C123.1 C140.2 R112.1 R434.1 U7.60(SNS5-)
SN6: C122.2 C125.1 R94.2 R437.1 U7.63(SNS6-)
VHIGH: C14.1 C15.2 C16.2 C19.2 C54.2 C55.2 C61.1 C75.2 C124.2 C127.2 C128.2 C136.1 C170.1 C171.1 C172.1 C173.1 C174.1 C175.1 C176.1 C177.1 C178.1 C179.1 C180.1 C181.1 C182.1 C183.1 C184.2 C185.2 C186.2 C187.2 C190.1 C191.1 E11.1 J1.1(TP) Q1.5(D) Q2.5(D) Q3.5(D) Q4.5(D) Q17.5(D) Q20.5(D) Q22.5(D) Q24.5(D) Q37.5(D) Q39.5(D) Q40.5(D) Q42.5(D) R1.1 R2.2 R29.2 R429.2 R464.2
VLOW: C20.1 C21.1 C22.2 C24.1 C25.2 C27.1 C47.1 C66.2 C72.2 C73.1 C74.1 C76.1 C107.1 C129.2 C131.1 C132.1 C133.2 C135.1 C137.1 C192.1 C193.1 D12.2(A) E23.1 J7.1(TP) J8.1(TP) J10.1(TP) R15.2 R414.1 R426.2 R432.2 R433.2 R434.2 R435.2 R436.2 R437.2 R454.1 R465.2 RS1.1 RS2.2 RS3.2 RS4.1 RS5.2 RS6.1
N16723613: C39.2 R29.1 U7.48(VHIGH)
N19632194: C11.2 R11.1 U7.6(ITHHIGH)
N19638427: C7.2 R11.2
N19643876: C6.2 R10.2
N19643878: C5.2 R10.1 U7.4(ITHLOW)
N19716351: R44.1 U7.53(FREQ)
N19723679: E21.1 R456.1 R457.2 U7.52(SYNC)
N19741175: E4.1 SW1.5 U7.54(BUCK)
N19757608: C46.1 L3.2 Q17.1(S) Q17.2(S) Q17.3(S) Q19.5(D) Q23.5(D) Q24.1(S) Q24.2(S) Q24.3(S) R65.1 U3.10(SW)
N19757627: Q19.4(G) Q23.4(G) R473.2
N19757656: Q18.4(G) Q21.4(G) R475.2
N19757658: C158.1 L4.2 Q18.5(D) Q20.1(S) Q20.2(S) Q20.3(S) Q21.5(D) Q22.1(S) Q22.2(S) Q22.3(S) R53.2 U4.10(SW)
N19757696: Q17.4(G) Q24.4(G) R472.2
N19757700: Q20.4(G) Q22.4(G) R474.2
N19757715: L3.1 R43.1 RS3.1
N19757716: L4.1 R49.1 RS4.2
N20240653: JP3.2 JP3.3 U7.51(MODE)
N20387706: R19.1 R20.2 U7.44(DRVSET)
N20536523: C148.2 E5.1 SW1.2 U7.11(SETCUR)
N21083681: R9.2 R15.1 U7.15(OVLOW)
N21925529: C196.2 R2.1 R8.2 U7.14(UVHIGH)
N21925625: C189.2 R1.2 R36.2 U7.13(OVHIGH)
N21963039: C12.2 E2.1 U7.10(IMON)
N21975323: E9.1 R18.1 U7.35(\\\\\\\\\\FAULT)
N22044941: R67.1 U3.12(BST)
N22044944: C46.2 D3.1(C) R67.2
N22379941: R472.1 U3.11(TG)
N22380043: C149.2 R398.2 R423.1 U3.5(Vcc)
N22380641: R397.1 U3.4(DT)
N22383858: R473.1 U3.8(BG)
N22388472: C152.1 L1.2 Q3.1(S) Q3.2(S) Q3.3(S) Q4.1(S) Q4.2(S) Q4.3(S) Q6.5(D) Q8.5(D) R31.1 U1.10(SW)
N22388518: Q3.4(G) Q4.4(G) R468.2
N22388576: L1.1 R39.1 RS1.2
N22388592: Q6.4(G) Q8.4(G) R467.2
N22389376: R401.1 U1.4(DT)
N22389391: R400.1 U1.12(BST)
N22389401: C152.2 D7.1(C) R400.2
N22389409: C153.2 R399.2 R424.1 U1.5(Vcc)
N22389462: R468.1 U1.11(TG)
N22390758: R467.1 U1.8(BG)
N22394410: C155.1 L2.2 Q1.1(S) Q1.2(S) Q1.3(S) Q2.1(S) Q2.2(S) Q2.3(S) Q5.5(D) Q7.5(D) R32.2 U2.10(SW)
N22394479: L2.1 R40.1 RS2.1
N22394488: Q1.4(G) Q2.4(G) R470.2
N22395761: R404.1 U2.4(DT)
N22395776: R403.1 U2.12(BST)
N22395778: C155.2 D8.1(C) R403.2
N22395792: C156.2 R402.2 R421.1 U2.5(Vcc)
N22395837: R470.1 U2.11(TG)
N22395899: R471.1 U2.8(BG)
N22398181: R407.1 U4.4(DT)
N22398196: R406.1 U4.12(BST)
N22398198: C158.2 D9.1(C) R406.2
N22398212: C159.2 R405.2 R422.1 U4.5(Vcc)
N22398257: R474.1 U4.11(TG)
N22398319: R475.1 U4.8(BG)
N22399790: R410.1 U5.4(DT)
N22399805: R409.1 U5.12(BST)
N22399807: C161.2 D10.1(C) R409.2
N22399821: C162.2 R408.2 R420.1 U5.5(Vcc)
N22399844: C161.1 L5.2 Q36.5(D) Q40.1(S) Q40.2(S) Q40.3(S) Q41.5(D) Q42.1(S) Q42.2(S) Q42.3(S) R98.1 U5.10(SW)
N22399866: R476.1 U5.11(TG)
N22401078: R413.1 U6.4(DT)
N22401093: R412.1 U6.12(BST)
N22401095: C164.2 D11.1(C) R412.2
N22401109: C165.2 R411.2 R419.1 U6.5(Vcc)
N22401132: C164.1 L6.2 Q35.5(D) Q37.1(S) Q37.2(S) Q37.3(S) Q38.5(D) Q39.1(S) Q39.2(S) Q39.3(S) R97.2 U6.10(SW)
N22401154: R478.1 U6.11(TG)
N22401949: L5.1 R93.1 RS5.1
N22401993: Q36.4(G) Q41.4(G) R477.2
N22402027: Q40.4(G) Q42.4(G) R476.2
N22403055: Q37.4(G) Q39.4(G) R478.2
N22403110: Q35.4(G) Q38.4(G) R479.2
N22403144: L6.1 R103.1 RS6.2
N22403783: R479.1 U6.8(BG)
N22408634: R477.1 U5.8(BG)
N22409295: C105.1 C168.1 D12.1(C) D13.1(C) E1.1 R414.2 U7.42(EXTVCC)
N22413112: E3.1 U7.50(CLKOUT)
N22413677: J6.4(SCK/SCL) R415.2
N22413687: J6.6(CS) R416.2
N22413689: J6.7(MOSI/SDA) R12.2
N22421972: C166.1 R427.1 R428.2 U7.3(VFBLOW)
N22421975: C166.2 R426.1 R427.2
N22422510: C167.1 C195.2 R430.2 R431.1 U7.7(VFBHIGH)
N22422512: C167.2 R429.1 R431.2
N22458225: Q5.4(G) Q7.4(G) R471.2
N22512291: R7.1 R17.2 U7.49(ILIM)
N22515467: R399.1 U1.3(FLTB)
N22517608: R402.1 U2.3(FLTB)
N22535148: R398.1 U3.3(FLTB)
N22535905: R408.1 U5.3(FLTB)
N22535990: R405.1 U4.3(FLTB)
N22536055: R411.1 U6.3(FLTB)
N22617523: R444.2 U1.1(PWM)
N22617555: R445.2 U1.2(EN)
N22617620: R442.2 U3.1(PWM)
N22617651: R443.2 U3.2(EN)
N22617690: R448.2 U2.1(PWM)
N22617743: R446.2 U2.2(EN)
N22617915: R447.2 U4.1(PWM)
N22617963: R449.2 U4.2(EN)
N22618047: R452.2 U5.1(PWM)
N22618079: R453.2 U5.2(EN)
N22618130: R450.2 U6.1(PWM)
N22618135: R451.2 U6.2(EN)
N22624600: J6.11(EESCL) R439.1 U8.6(SCL)
N22624602: JP21.1 R440.1 U8.7(WP)
N22624620: J6.9(EESDA) R441.1 U8.5(SDA)
N22624638: C169.1 J6.10(EEVCC) R439.2 R440.2 R441.2 U8.8(VCC)
N22721820: C188.2 JP22.1 JP23.1 JP24.1 R454.2 R455.1
N22730832: E27.1 R455.2
N22752069: R438.1 SW1.3
N22752195: R425.2 SW1.1
N22962431: JP25.1 R464.1 Z1.1(C)
N22963355: D14.2(A) JP25.2
N22975126: R469.1 SW1.4
N23047807: C9.2 U7.1(SS)

Not connected (* = marked no-connect by the designer): J6 1(V+) 14(GPIO_1); JP4 1*; JP21 3; U1 9(NC); U2 9(NC); U3 9(NC); U4 9(NC); U5 9(NC); U6 9(NC); U7 2(NC) 8(NC) 12(NC) 26(NC) 41(NC) 43(NC) 47(NC) 55(NC)

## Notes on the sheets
sheet 1
- 3528
- Note:
  ILIM SETTING is 3/4 * V5
- Fsw = 150kHz, typical
- TO DC590B or
  LINDUINO DC2026C
- OPT
- IDENTITY EEPROM
sheet 2
- CVE2622H
- CVE2622H
- 25V
- 1210
- X5R
- 25V
- 1210
- X5R
- CVE2622H
- CVE2622H
- 25V
- 25V
- 1210
- 1210
- X5R
- X5R
- CVE2622H
- CVE2622H
- 25V
- 1210
- X5R
- 25V
- 1210
- X5R
- When operating as a
  CV boost converter,
  10mF or more of
  external bulk
  capacitance is
  recommended across
  VLOW.
- 14V/180A
- Note: JP22 – JP24 are for optional DC fans.
- Optional DCR sensing components
sheet 3
- PCA ADDITIONAL PARTS
